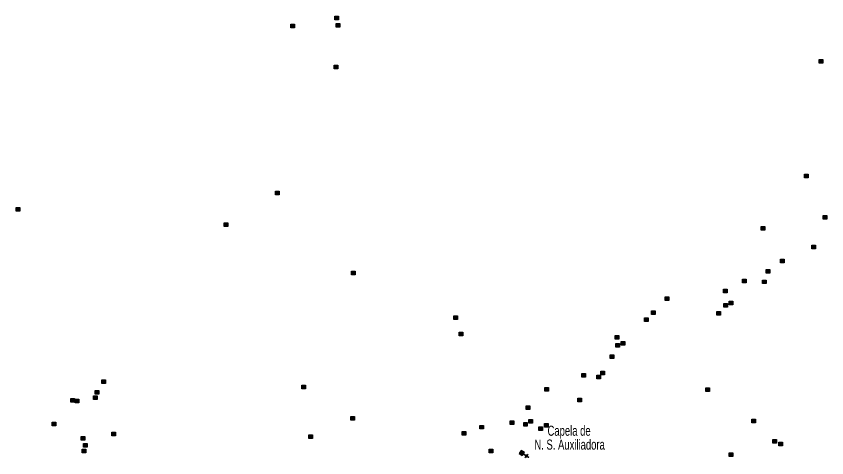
# Model space of a CAD drawing. Extents: x 649.2 to 674.4, y 7040 to 7068.1.
# Drawn here: x 661.68 to 668.1, y 7043.51 to 7047 of the extents above; entities that cross this region are included whole.
import ezdxf

# ---------------------------------------------------------------- set-up
doc = ezdxf.new("R2010")
doc.units = 0
doc.header["$LTSCALE"] = 0.032
doc.layers.add('2', color=7, linetype='Continuous', lineweight=25)
doc.layers.add('6', color=7, linetype='Continuous', lineweight=25)
doc.layers.add('61', color=7, linetype='Continuous')

msp = doc.modelspace()

# ---------------------------------------------------------------- hatches: boundary and pattern name
at = {"layer": '2'}
for points in [[(664.2073, 7047.003), (664.2363, 7047.003), (664.2363, 7046.974), (664.2073, 7046.974)], [(663.8591, 7046.9408), (663.8881, 7046.9408), (663.8881, 7046.9118), (663.8591, 7046.9118)], [(664.2189, 7046.9452), (664.2479, 7046.9452), (664.2479, 7046.9162), (664.2189, 7046.9162)], [(668.0404, 7046.6601), (668.0694, 7046.6601), (668.0694, 7046.6311), (668.0404, 7046.6311)], [(664.203, 7046.6157), (664.232, 7046.6157), (664.232, 7046.5867), (664.203, 7046.5867)], [(667.9256, 7045.753), (667.9546, 7045.753), (667.9546, 7045.724), (667.9256, 7045.724)], [(663.7386, 7045.6176), (663.7676, 7045.6176), (663.7676, 7045.5886), (663.7386, 7045.5886)], [(661.6846, 7045.4876), (661.7136, 7045.4876), (661.7136, 7045.4586), (661.6846, 7045.4586)], [(668.0727, 7045.4245), (668.1017, 7045.4245), (668.1017, 7045.3955), (668.0727, 7045.3955)], [(663.3321, 7045.366), (663.3611, 7045.366), (663.3611, 7045.337), (663.3321, 7045.337)], [(667.5818, 7045.3368), (667.6108, 7045.3368), (667.6108, 7045.3078), (667.5818, 7045.3078)], [(667.9827, 7045.1907), (668.0117, 7045.1907), (668.0117, 7045.1617), (667.9827, 7045.1617)], [(667.7361, 7045.0797), (667.7651, 7045.0797), (667.7651, 7045.0507), (667.7361, 7045.0507)], [(664.3378, 7044.9832), (664.3668, 7044.9832), (664.3668, 7044.9542), (664.3378, 7044.9542)], [(667.6208, 7044.9978), (667.6498, 7044.9978), (667.6498, 7044.9688), (667.6208, 7044.9688)], [(667.4346, 7044.9215), (667.4636, 7044.9215), (667.4636, 7044.8925), (667.4346, 7044.8925)], [(667.5936, 7044.9142), (667.6226, 7044.9142), (667.6226, 7044.8852), (667.5936, 7044.8852)], [(667.2848, 7044.8415), (667.3138, 7044.8415), (667.3138, 7044.8125), (667.2848, 7044.8125)], [(666.8209, 7044.7807), (666.8499, 7044.7807), (666.8499, 7044.7517), (666.8209, 7044.7517)], [(667.2875, 7044.728), (667.3165, 7044.728), (667.3165, 7044.699), (667.2875, 7044.699)], [(667.3293, 7044.7461), (667.3583, 7044.7461), (667.3583, 7044.7171), (667.3293, 7044.7171)], [(665.1499, 7044.6307), (665.1789, 7044.6307), (665.1789, 7044.6017), (665.1499, 7044.6017)], [(666.7141, 7044.671), (666.7431, 7044.671), (666.7431, 7044.642), (666.7141, 7044.642)], [(667.2312, 7044.6644), (667.2602, 7044.6644), (667.2602, 7044.6354), (667.2312, 7044.6354)], [(666.6592, 7044.6148), (666.6882, 7044.6148), (666.6882, 7044.5858), (666.6592, 7044.5858)], [(665.1921, 7044.5014), (665.2211, 7044.5014), (665.2211, 7044.4724), (665.1921, 7044.4724)], [(666.4273, 7044.4756), (666.4563, 7044.4756), (666.4563, 7044.4466), (666.4273, 7044.4466)], [(666.4315, 7044.4109), (666.4605, 7044.4109), (666.4605, 7044.3819), (666.4315, 7044.3819)], [(666.4751, 7044.4278), (666.5041, 7044.4278), (666.5041, 7044.3988), (666.4751, 7044.3988)], [(666.3879, 7044.3223), (666.4169, 7044.3223), (666.4169, 7044.2933), (666.3879, 7044.2933)], [(666.3134, 7044.1916), (666.3424, 7044.1916), (666.3424, 7044.1626), (666.3134, 7044.1626)], [(662.3633, 7044.1227), (662.3923, 7044.1227), (662.3923, 7044.0937), (662.3633, 7044.0937)], [(666.1615, 7044.1733), (666.1905, 7044.1733), (666.1905, 7044.1443), (666.1615, 7044.1443)], [(666.2824, 7044.1606), (666.3114, 7044.1606), (666.3114, 7044.1316), (666.2824, 7044.1316)], [(663.9446, 7044.0826), (663.9736, 7044.0826), (663.9736, 7044.0536), (663.9446, 7044.0536)], [(665.8703, 7044.0628), (665.8993, 7044.0628), (665.8993, 7044.0338), (665.8703, 7044.0338)], [(667.1442, 7044.0614), (667.1732, 7044.0614), (667.1732, 7044.0324), (667.1442, 7044.0324)], [(662.2958, 7043.9963), (662.3248, 7043.9963), (662.3248, 7043.9673), (662.2958, 7043.9673)], [(662.3093, 7044.0405), (662.3383, 7044.0405), (662.3383, 7044.0115), (662.3093, 7044.0115)], [(662.1167, 7043.9767), (662.1457, 7043.9767), (662.1457, 7043.9477), (662.1167, 7043.9477)], [(662.1511, 7043.9694), (662.1801, 7043.9694), (662.1801, 7043.9404), (662.1511, 7043.9404)], [(666.13, 7043.9793), (666.159, 7043.9793), (666.159, 7043.9503), (666.13, 7043.9503)], [(665.7205, 7043.9171), (665.7495, 7043.9171), (665.7495, 7043.8881), (665.7205, 7043.8881)], [(664.3349, 7043.8345), (664.3639, 7043.8345), (664.3639, 7043.8055), (664.3349, 7043.8055)], [(665.5947, 7043.7991), (665.6237, 7043.7991), (665.6237, 7043.7701), (665.5947, 7043.7701)], [(665.7417, 7043.8097), (665.7707, 7043.8097), (665.7707, 7043.7807), (665.7417, 7043.7807)], [(667.5071, 7043.8113), (667.5361, 7043.8113), (667.5361, 7043.7823), (667.5071, 7043.7823)], [(661.9683, 7043.7878), (661.9973, 7043.7878), (661.9973, 7043.7588), (661.9683, 7043.7588)], [(665.3562, 7043.7634), (665.3852, 7043.7634), (665.3852, 7043.7344), (665.3562, 7043.7344)], [(665.702, 7043.7846), (665.731, 7043.7846), (665.731, 7043.7556), (665.702, 7043.7556)], [(665.8226, 7043.7514), (665.8516, 7043.7514), (665.8516, 7043.7224), (665.8226, 7043.7224)], [(665.8663, 7043.7779), (665.8953, 7043.7779), (665.8953, 7043.7489), (665.8663, 7043.7489)], [(662.1977, 7043.6737), (662.2267, 7043.6737), (662.2267, 7043.6447), (662.1977, 7043.6447)], [(662.4418, 7043.7081), (662.4708, 7043.7081), (662.4708, 7043.6791), (662.4418, 7043.6791)], [(664.0011, 7043.6889), (664.0301, 7043.6889), (664.0301, 7043.6599), (664.0011, 7043.6599)], [(665.2162, 7043.714), (665.2452, 7043.714), (665.2452, 7043.685), (665.2162, 7043.685)], [(662.2166, 7043.6202), (662.2456, 7043.6202), (662.2456, 7043.5912), (662.2166, 7043.5912)], [(667.6738, 7043.6514), (667.7028, 7043.6514), (667.7028, 7043.6224), (667.6738, 7043.6224)], [(667.7231, 7043.6294), (667.7521, 7043.6294), (667.7521, 7043.6004), (667.7231, 7043.6004)], [(662.2073, 7043.5739), (662.2363, 7043.5739), (662.2363, 7043.5449), (662.2073, 7043.5449)], [(665.4281, 7043.5745), (665.4571, 7043.5745), (665.4571, 7043.5455), (665.4281, 7043.5455)], [(667.3277, 7043.5466), (667.3567, 7043.5466), (667.3567, 7043.5176), (667.3277, 7043.5176)]]:
    msp.add_hatch(color=256, dxfattribs=at).paths.add_polyline_path(points)
at = {"layer": '6'}
for points in [[(665.7073, 7043.549), (665.6818, 7043.565), (665.6659, 7043.5396), (665.6914, 7043.5236)], [(665.6979, 7043.5342), (665.7006, 7043.5385), (665.7239, 7043.5238), (665.7306, 7043.5344), (665.7348, 7043.5317), (665.7281, 7043.5212), (665.7429, 7043.5118), (665.7403, 7043.5076), (665.7254, 7043.5169), (665.7189, 7043.5064), (665.7146, 7043.509), (665.7212, 7043.5196)]]:
    msp.add_hatch(color=256, dxfattribs=at).paths.add_polyline_path(points)

# ---------------------------------------------------------------- linework, layer by layer
at = {"layer": '2'}
for points in [[(664.2073, 7047.003), (664.2363, 7047.003), (664.2363, 7046.974), (664.2073, 7046.974)], [(663.8591, 7046.9408), (663.8881, 7046.9408), (663.8881, 7046.9118), (663.8591, 7046.9118)], [(664.2189, 7046.9452), (664.2479, 7046.9452), (664.2479, 7046.9162), (664.2189, 7046.9162)], [(668.0404, 7046.6601), (668.0694, 7046.6601), (668.0694, 7046.6311), (668.0404, 7046.6311)], [(664.203, 7046.6157), (664.232, 7046.6157), (664.232, 7046.5867), (664.203, 7046.5867)], [(667.9256, 7045.753), (667.9546, 7045.753), (667.9546, 7045.724), (667.9256, 7045.724)], [(663.7386, 7045.6176), (663.7676, 7045.6176), (663.7676, 7045.5886), (663.7386, 7045.5886)], [(661.6846, 7045.4876), (661.7136, 7045.4876), (661.7136, 7045.4586), (661.6846, 7045.4586)], [(668.0727, 7045.4245), (668.1017, 7045.4245), (668.1017, 7045.3955), (668.0727, 7045.3955)], [(663.3321, 7045.366), (663.3611, 7045.366), (663.3611, 7045.337), (663.3321, 7045.337)], [(667.5818, 7045.3368), (667.6108, 7045.3368), (667.6108, 7045.3078), (667.5818, 7045.3078)], [(667.9827, 7045.1907), (668.0117, 7045.1907), (668.0117, 7045.1617), (667.9827, 7045.1617)], [(667.7361, 7045.0797), (667.7651, 7045.0797), (667.7651, 7045.0507), (667.7361, 7045.0507)], [(664.3378, 7044.9832), (664.3668, 7044.9832), (664.3668, 7044.9542), (664.3378, 7044.9542)], [(667.6208, 7044.9978), (667.6498, 7044.9978), (667.6498, 7044.9688), (667.6208, 7044.9688)], [(667.4346, 7044.9215), (667.4636, 7044.9215), (667.4636, 7044.8925), (667.4346, 7044.8925)], [(667.5936, 7044.9142), (667.6226, 7044.9142), (667.6226, 7044.8852), (667.5936, 7044.8852)], [(667.2848, 7044.8415), (667.3138, 7044.8415), (667.3138, 7044.8125), (667.2848, 7044.8125)], [(666.8209, 7044.7807), (666.8499, 7044.7807), (666.8499, 7044.7517), (666.8209, 7044.7517)], [(667.2875, 7044.728), (667.3165, 7044.728), (667.3165, 7044.699), (667.2875, 7044.699)], [(667.3293, 7044.7461), (667.3583, 7044.7461), (667.3583, 7044.7171), (667.3293, 7044.7171)], [(665.1499, 7044.6307), (665.1789, 7044.6307), (665.1789, 7044.6017), (665.1499, 7044.6017)], [(666.7141, 7044.671), (666.7431, 7044.671), (666.7431, 7044.642), (666.7141, 7044.642)], [(667.2312, 7044.6644), (667.2602, 7044.6644), (667.2602, 7044.6354), (667.2312, 7044.6354)], [(666.6592, 7044.6148), (666.6882, 7044.6148), (666.6882, 7044.5858), (666.6592, 7044.5858)], [(665.1921, 7044.5014), (665.2211, 7044.5014), (665.2211, 7044.4724), (665.1921, 7044.4724)], [(666.4273, 7044.4756), (666.4563, 7044.4756), (666.4563, 7044.4466), (666.4273, 7044.4466)], [(666.4315, 7044.4109), (666.4605, 7044.4109), (666.4605, 7044.3819), (666.4315, 7044.3819)], [(666.4751, 7044.4278), (666.5041, 7044.4278), (666.5041, 7044.3988), (666.4751, 7044.3988)], [(666.3879, 7044.3223), (666.4169, 7044.3223), (666.4169, 7044.2933), (666.3879, 7044.2933)], [(666.3134, 7044.1916), (666.3424, 7044.1916), (666.3424, 7044.1626), (666.3134, 7044.1626)], [(662.3633, 7044.1227), (662.3923, 7044.1227), (662.3923, 7044.0937), (662.3633, 7044.0937)], [(666.1615, 7044.1733), (666.1905, 7044.1733), (666.1905, 7044.1443), (666.1615, 7044.1443)], [(666.2824, 7044.1606), (666.3114, 7044.1606), (666.3114, 7044.1316), (666.2824, 7044.1316)], [(663.9446, 7044.0826), (663.9736, 7044.0826), (663.9736, 7044.0536), (663.9446, 7044.0536)], [(665.8703, 7044.0628), (665.8993, 7044.0628), (665.8993, 7044.0338), (665.8703, 7044.0338)], [(667.1442, 7044.0614), (667.1732, 7044.0614), (667.1732, 7044.0324), (667.1442, 7044.0324)], [(662.2958, 7043.9963), (662.3248, 7043.9963), (662.3248, 7043.9673), (662.2958, 7043.9673)], [(662.3093, 7044.0405), (662.3383, 7044.0405), (662.3383, 7044.0115), (662.3093, 7044.0115)], [(662.1167, 7043.9767), (662.1457, 7043.9767), (662.1457, 7043.9477), (662.1167, 7043.9477)], [(662.1511, 7043.9694), (662.1801, 7043.9694), (662.1801, 7043.9404), (662.1511, 7043.9404)], [(666.13, 7043.9793), (666.159, 7043.9793), (666.159, 7043.9503), (666.13, 7043.9503)], [(665.7205, 7043.9171), (665.7495, 7043.9171), (665.7495, 7043.8881), (665.7205, 7043.8881)], [(664.3349, 7043.8345), (664.3639, 7043.8345), (664.3639, 7043.8055), (664.3349, 7043.8055)], [(665.5947, 7043.7991), (665.6237, 7043.7991), (665.6237, 7043.7701), (665.5947, 7043.7701)], [(665.7417, 7043.8097), (665.7707, 7043.8097), (665.7707, 7043.7807), (665.7417, 7043.7807)], [(667.5071, 7043.8113), (667.5361, 7043.8113), (667.5361, 7043.7823), (667.5071, 7043.7823)], [(661.9683, 7043.7878), (661.9973, 7043.7878), (661.9973, 7043.7588), (661.9683, 7043.7588)], [(665.3562, 7043.7634), (665.3852, 7043.7634), (665.3852, 7043.7344), (665.3562, 7043.7344)], [(665.702, 7043.7846), (665.731, 7043.7846), (665.731, 7043.7556), (665.702, 7043.7556)], [(665.8226, 7043.7514), (665.8516, 7043.7514), (665.8516, 7043.7224), (665.8226, 7043.7224)], [(665.8663, 7043.7779), (665.8953, 7043.7779), (665.8953, 7043.7489), (665.8663, 7043.7489)], [(662.1977, 7043.6737), (662.2267, 7043.6737), (662.2267, 7043.6447), (662.1977, 7043.6447)], [(662.4418, 7043.7081), (662.4708, 7043.7081), (662.4708, 7043.6791), (662.4418, 7043.6791)], [(664.0011, 7043.6889), (664.0301, 7043.6889), (664.0301, 7043.6599), (664.0011, 7043.6599)], [(665.2162, 7043.714), (665.2452, 7043.714), (665.2452, 7043.685), (665.2162, 7043.685)], [(662.2166, 7043.6202), (662.2456, 7043.6202), (662.2456, 7043.5912), (662.2166, 7043.5912)], [(667.6738, 7043.6514), (667.7028, 7043.6514), (667.7028, 7043.6224), (667.6738, 7043.6224)], [(667.7231, 7043.6294), (667.7521, 7043.6294), (667.7521, 7043.6004), (667.7231, 7043.6004)], [(662.2073, 7043.5739), (662.2363, 7043.5739), (662.2363, 7043.5449), (662.2073, 7043.5449)], [(665.4281, 7043.5745), (665.4571, 7043.5745), (665.4571, 7043.5455), (665.4281, 7043.5455)], [(667.3277, 7043.5466), (667.3567, 7043.5466), (667.3567, 7043.5176), (667.3277, 7043.5176)]]:
    msp.add_lwpolyline(points, close=True, dxfattribs=at)
at = {"layer": '6'}
for points in [[(665.7073, 7043.549), (665.6818, 7043.565), (665.6659, 7043.5396), (665.6914, 7043.5236)], [(665.6979, 7043.5342), (665.7006, 7043.5385), (665.7239, 7043.5238), (665.7306, 7043.5344), (665.7348, 7043.5317), (665.7281, 7043.5212), (665.7429, 7043.5118), (665.7403, 7043.5076), (665.7254, 7043.5169), (665.7189, 7043.5064), (665.7146, 7043.509), (665.7212, 7043.5196)]]:
    msp.add_lwpolyline(points, close=True, dxfattribs=at)

# ---------------------------------------------------------------- texts
at = {"layer": '61', "width": 0.7}
for s, p in [('     Capela de', (665.7869, 7043.6809)), ('N. S. Auxiliadora', (665.7869, 7043.5709))]:
    msp.add_text(s, height=0.08, dxfattribs=at).set_placement(p)

doc.saveas('drawing.dxf')
